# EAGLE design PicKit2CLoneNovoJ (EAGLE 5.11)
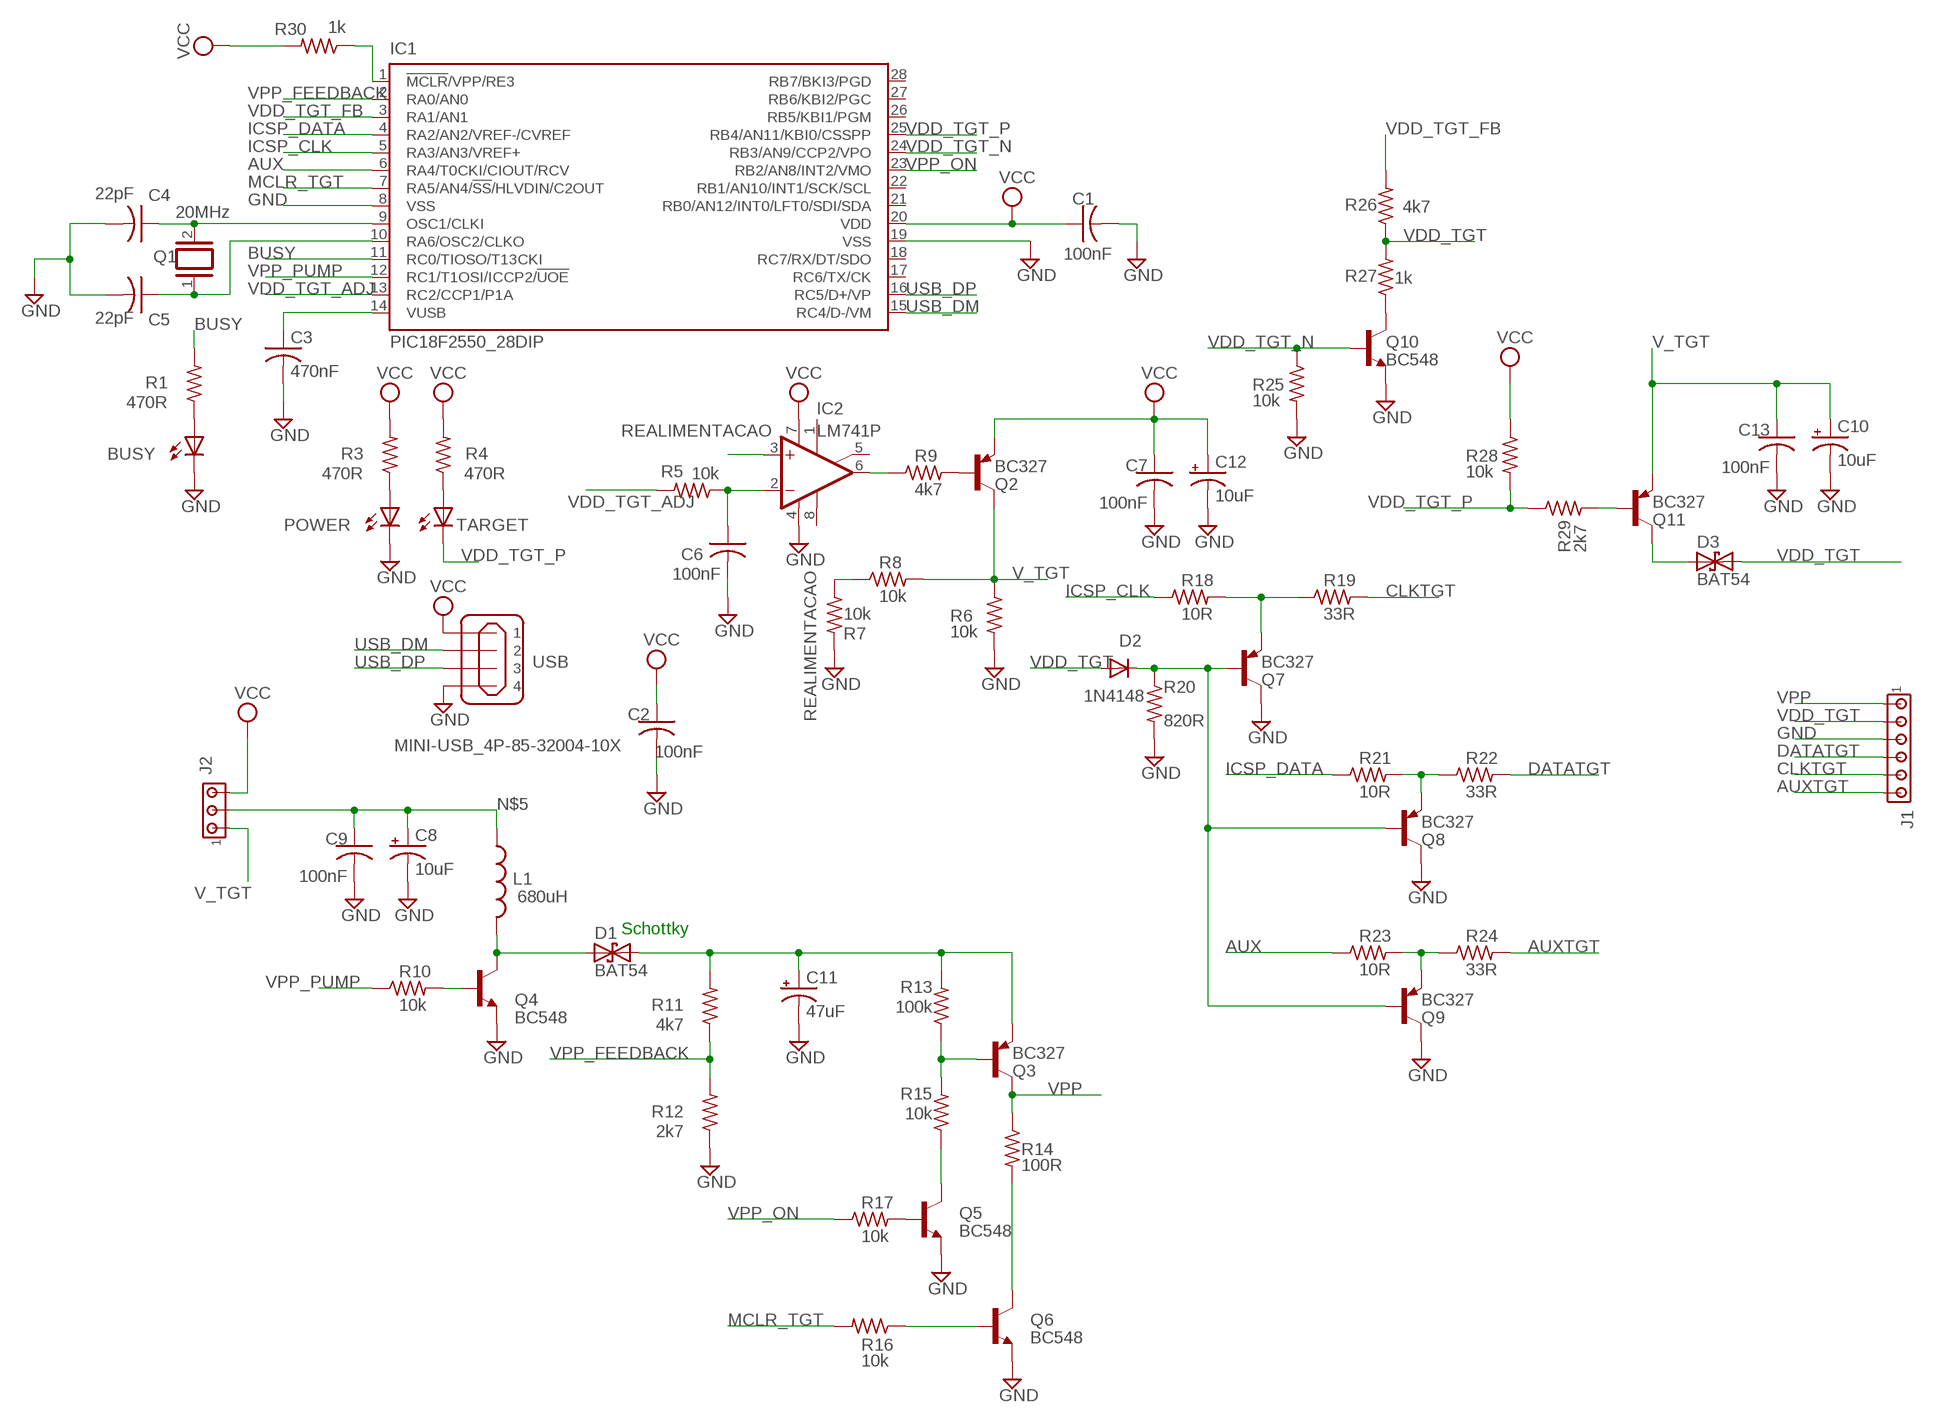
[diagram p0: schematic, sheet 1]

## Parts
BUSY  LED5MM  [LED5MM]
C1  100nF  C-US025-030X050  [C025-030X050]
C2  100nF  C-US025-030X050  [C025-030X050]
C3  470nF  C-US025-030X050  [C025-030X050]
C4  22pF  C-US025-025X050  [C025-025X050]
C5  22pF  C-US025-025X050  [C025-025X050]
C6  100nF  C-US025-030X050  [C025-030X050]
C7  100nF  C-US025-030X050  [C025-030X050]
C8  10uF  CPOL-USE1.8-4  [E1,8-4]
C9  100nF  C-US025-030X050  [C025-030X050]
C10  10uF  CPOL-USE1.8-4  [E1,8-4]
C11  47uF  CPOL-USE2.5-7  [E2,5-7]
C12  10uF  CPOL-USE1.8-4  [E1,8-4]
C13  100nF  C-US025-030X050  [C025-030X050]
D1  BAT54  DIODE_SCHOTTKY2-F126-12  [F126Z12]
D2  1N4148  1N4148DO35-10  [DO35-10]
D3  BAT54  DIODE_SCHOTTKY2-F126-12  [F126Z12]
IC1  PIC18F2550_28DIP  [DIL28-3]
IC2  LM741P  [DIL08]
J1  MTA06-100  [10X06MTA]
J2  MTA03-100  [10X03MTA]
L1  680uH  L-US0207/10  [0207/10]
POWER  LED5MM  [LED5MM]
Q1  20MHz  XTAL/S  [QS]
Q2  BC327  [TO92]
Q3  BC327  [TO92]
Q4  BC548  [TO92-EBC]
Q5  BC548  [TO92-EBC]
Q6  BC548  [TO92-EBC]
Q7  BC327  [TO92]
Q8  BC327  [TO92]
Q9  BC327  [TO92]
Q10  BC548  [TO92-EBC]
Q11  BC327  [TO92]
R1  470R  R-US_0207/10  [0207/10]
R3  470R  R-US_0207/10  [0207/10]
R4  470R  R-US_0207/10  [0207/10]
R5  10k  R-US_0207/10  [0207/10]
R6  10k  R-US_0207/10  [0207/10]
R7  10k  R-US_0207/10  [0207/10]
R8  10k  R-US_0207/10  [0207/10]
R9  4k7  R-US_0207/10  [0207/10]
R10  10k  R-US_0207/10  [0207/10]
R11  4k7  R-US_0207/10  [0207/10]
R12  2k7  R-US_0207/10  [0207/10]
R13  100k  R-US_0207/10  [0207/10]
R14  100R  R-US_0207/10  [0207/10]
R15  10k  R-US_0207/10  [0207/10]
R16  10k  R-US_0207/10  [0207/10]
R17  10k  R-US_0207/10  [0207/10]
R18  10R  R-US_0207/10  [0207/10]
R19  33R  R-US_0207/10  [0207/10]
R20  820R  R-US_0207/10  [0207/10]
R21  10R  R-US_0207/10  [0207/10]
R22  33R  R-US_0207/10  [0207/10]
R23  10R  R-US_0207/10  [0207/10]
R24  33R  R-US_0207/10  [0207/10]
R25  10k  R-US_0207/10  [0207/10]
R26  4k7  R-US_0207/10  [0207/10]
R27  1k  R-US_0207/10  [0207/10]
R28  10k  R-US_0207/10  [0207/10]
R29  2k7  R-US_0207/10  [0207/10]
R30  1k  R-US_0207/10  [0207/10]
TARGET  LED5MM  [LED5MM]
USB  MINI-USB_4P-85-32004-10X  [85-32004-10X]

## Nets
AUX: IC1.6(RA4/T0CKI/CIOUT/RCV) R23.1
AUXTGT: J1.1 R24.2
BUSY: IC1.11(RC0/TIOSO/T13CKI) R1.2
CLKTGT: J1.2 R19.2
DATATGT: J1.3 R22.2
GND: BUSY.K(C) C1.2 C2.2 C3.2 C4.2 C5.2 C6.2 C7.2 C8.- C9.2 C10.- C11.- C12.- C13.2 IC1.8(VSS) IC1.19(VSS) IC2.4(V-) J1.4 POWER.K(C) Q4.E Q5.E Q6.E Q7.3(C) Q8.3(C) Q9.3(C) Q10.E R6.2 R7.2 R12.1 R20.2 R25.2 USB.4
ICSP_CLK: IC1.5(RA3/AN3/VREF+) R18.1
ICSP_DATA: IC1.4(RA2/AN2/VREF-/CVREF) R21.1
MCLR_TGT: IC1.7(RA5/AN4/!SS!/HLVDIN/C2OUT) R16.2
N$1: C4.1 IC1.9(OSC1/CLKI) Q1.2
N$2: C5.1 IC1.10(RA6/OSC2/CLKO) Q1.1
N$3: BUSY.A R1.1
N$4: C3.1 IC1.14(VUSB)
N$5: C8.+ C9.1 J2.2 L1.1
N$7: POWER.A R3.1
N$8: R4.1 TARGET.A
N$9: C6.1 IC2.2(-IN) R5.1
N$10: Q2.2(B) R9.2
N$11: IC2.6(OUT) R9.1
N$12: D1.A L1.2 Q4.C
N$14: IC1.1(!MCLR!/VPP/RE3) R30.1
N$15: Q4.B R10.2
N$16: Q5.C R15.1
N$17: C11.+ D1.C Q3.1(E) R11.2 R13.2
N$18: Q5.B R17.2
N$19: Q3.2(B) R13.1 R15.2
N$20: D2.C Q7.2(B) Q8.2(B) Q9.2(B) R20.1
N$21: Q6.B R16.1
N$22: Q7.1(E) R18.2 R19.1
N$23: Q6.C R14.2
N$24: Q8.1(E) R21.2 R22.1
N$25: Q9.1(E) R23.2 R24.1
N$26: Q10.C R27.1
N$27: Q11.2(B) R29.2
N$30: D3.A Q11.3(C)
REALIMENTACAO: IC2.3(+IN) R7.1 R8.1
USB_DM: IC1.15(RC4/D-/VM) USB.2
USB_DP: IC1.16(RC5/D+/VP) USB.3
V_TGT: C10.+ C13.1 J2.1 Q2.3(C) Q11.1(E) R6.1 R8.2
VCC: C1.1 C2.1 C7.1 C12.+ IC1.20(VDD) IC2.7(V+) J2.3 Q2.1(E) R3.2 R4.2 R28.1 R30.2 USB.1
VDD_TGT: D2.A D3.C J1.5 R26.1 R27.2
VDD_TGT_ADJ: IC1.13(RC2/CCP1/P1A) R5.2
VDD_TGT_FB: IC1.3(RA1/AN1) R26.2
VDD_TGT_N: IC1.24(RB3/AN9/CCP2/VPO) Q10.B R25.1
VDD_TGT_P: IC1.25(RB4/AN11/KBI0/CSSPP) R28.2 R29.1 TARGET.K(C)
VPP: J1.6 Q3.3(C) R14.1
VPP_FEEDBACK: IC1.2(RA0/AN0) R11.1 R12.2
VPP_ON: IC1.23(RB2/AN8/INT2/VMO) R17.1
VPP_PUMP: IC1.12(RC1/T1OSI/ICCP2/!UOE) R10.1
Unconnected: IC1.17(RC6/TX/CK) IC1.18(RC7/RX/DT/SDO) IC1.21(RB0/AN12/INT0/LFT0/SDI/SDA) IC1.22(RB1/AN10/INT1/SCK/SCL) IC1.26(RB5/KBI1/PGM) IC1.27(RB6/KBI2/PGC) IC1.28(RB7/BKI3/PGD) IC2.1(ON1) IC2.5(ON2) IC2.8(OPT)

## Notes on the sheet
- Schottky

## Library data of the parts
BUSY POWER TARGET = led:LED: LED
C1-C7 C9 C13 = rcl:C-US: CAPACITOR, American symbol
C8 C10-C12 = resistor:CPOL-US: POLARIZED CAPACITOR, American symbol
D1 D3 = diode:DIODE_SCHOTTKY2-: Schottky Bidirectional Diode
D2 = diode:1N4148: DIODE
IC1 = microchip:PIC18F2*_28: USB Microcontrollers with nanoWatt Technology High-Performance, Enhanced Flash, 28/40/44-Pin, Source: http://ww1.microchip.com/downloads/en/devicedoc/39632c.pdf; MF: MICROCHIP; MPN: PIC18F2550-I/SP; OC_FARNELL: 1523822; OC_NEWARK: 80K6054
IC2 = linear:*741: OP AMP
J1 = con-amp:MTA06-100: AMP connector; OC_FARNELL: unknown; OC_NEWARK: unknown
J2 = con-amp:MTA03-100: AMP connector; OC_FARNELL: unknown; OC_NEWARK: unknown
L1 = rcl:L-US: INDUCTOR, American symbol
Q1 = special:XTAL/S: CRYSTAL
Q2 Q3 Q7-Q9 Q11 = transistor-pnp:BC327: PNP Transistor
Q4-Q6 Q10 = transistor-npn:BC548*: NPN Transistor
R1 R3-R30 = rcl:R-US_: RESISTOR, American symbol
USB = con-cypressindustries:MINI-USB_4P-: MINI USB 4 Pol. Source: www.cypressindustries.com; OC_FARNELL: unknown; OC_NEWARK: unknown

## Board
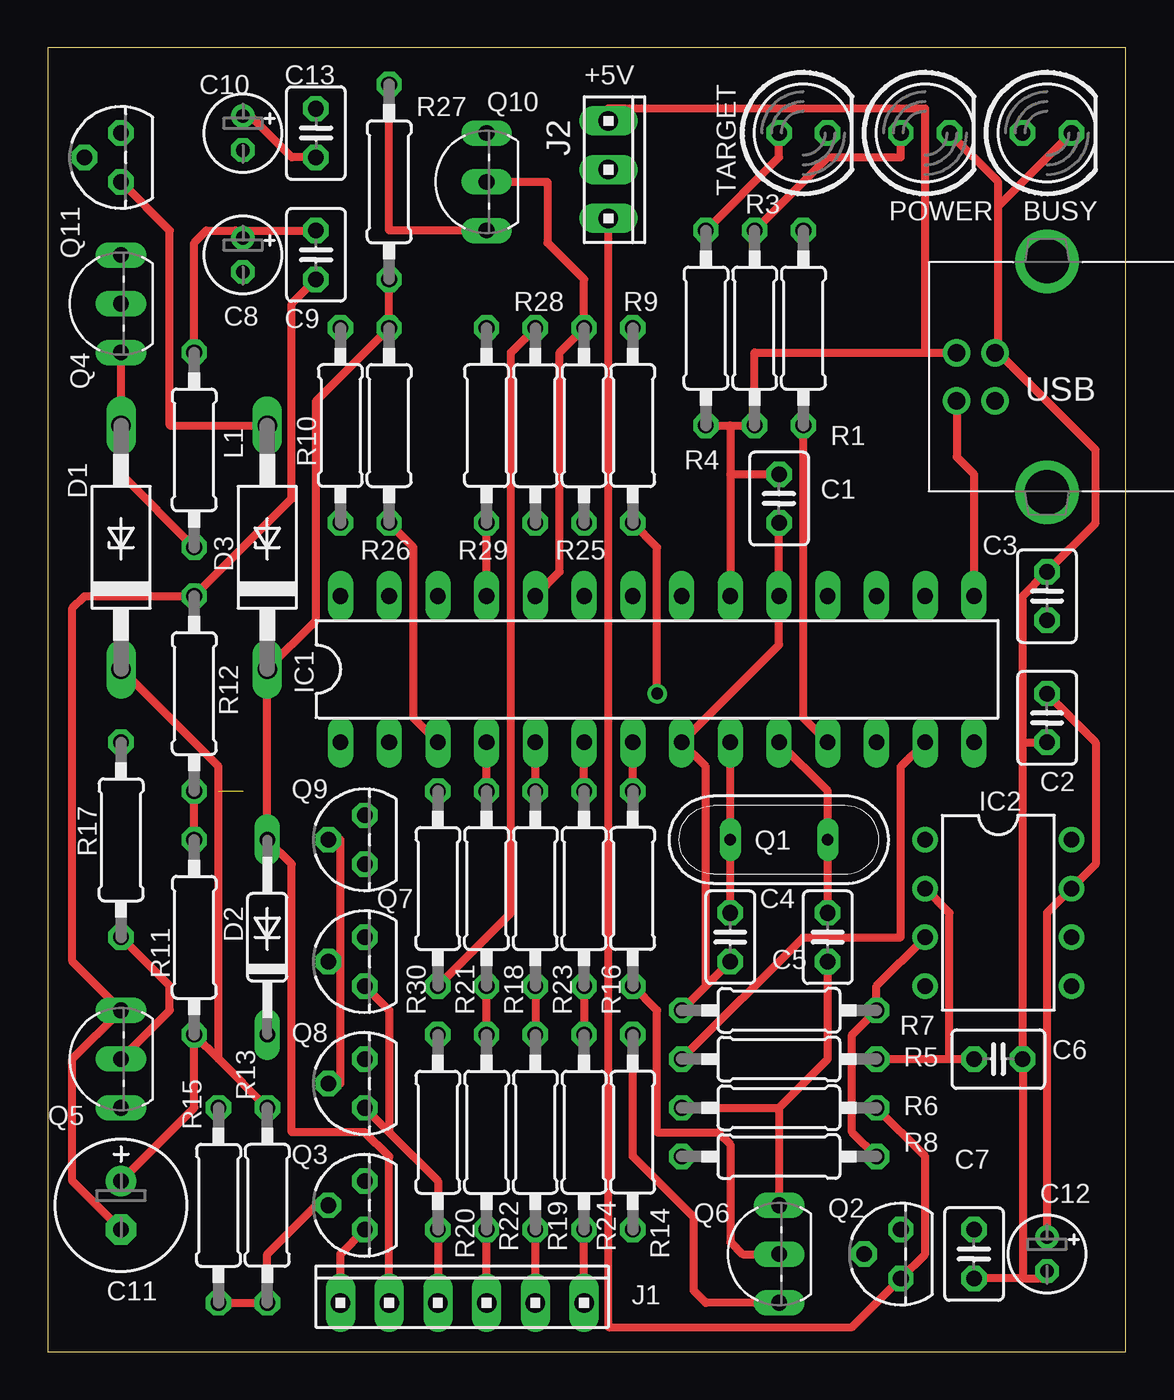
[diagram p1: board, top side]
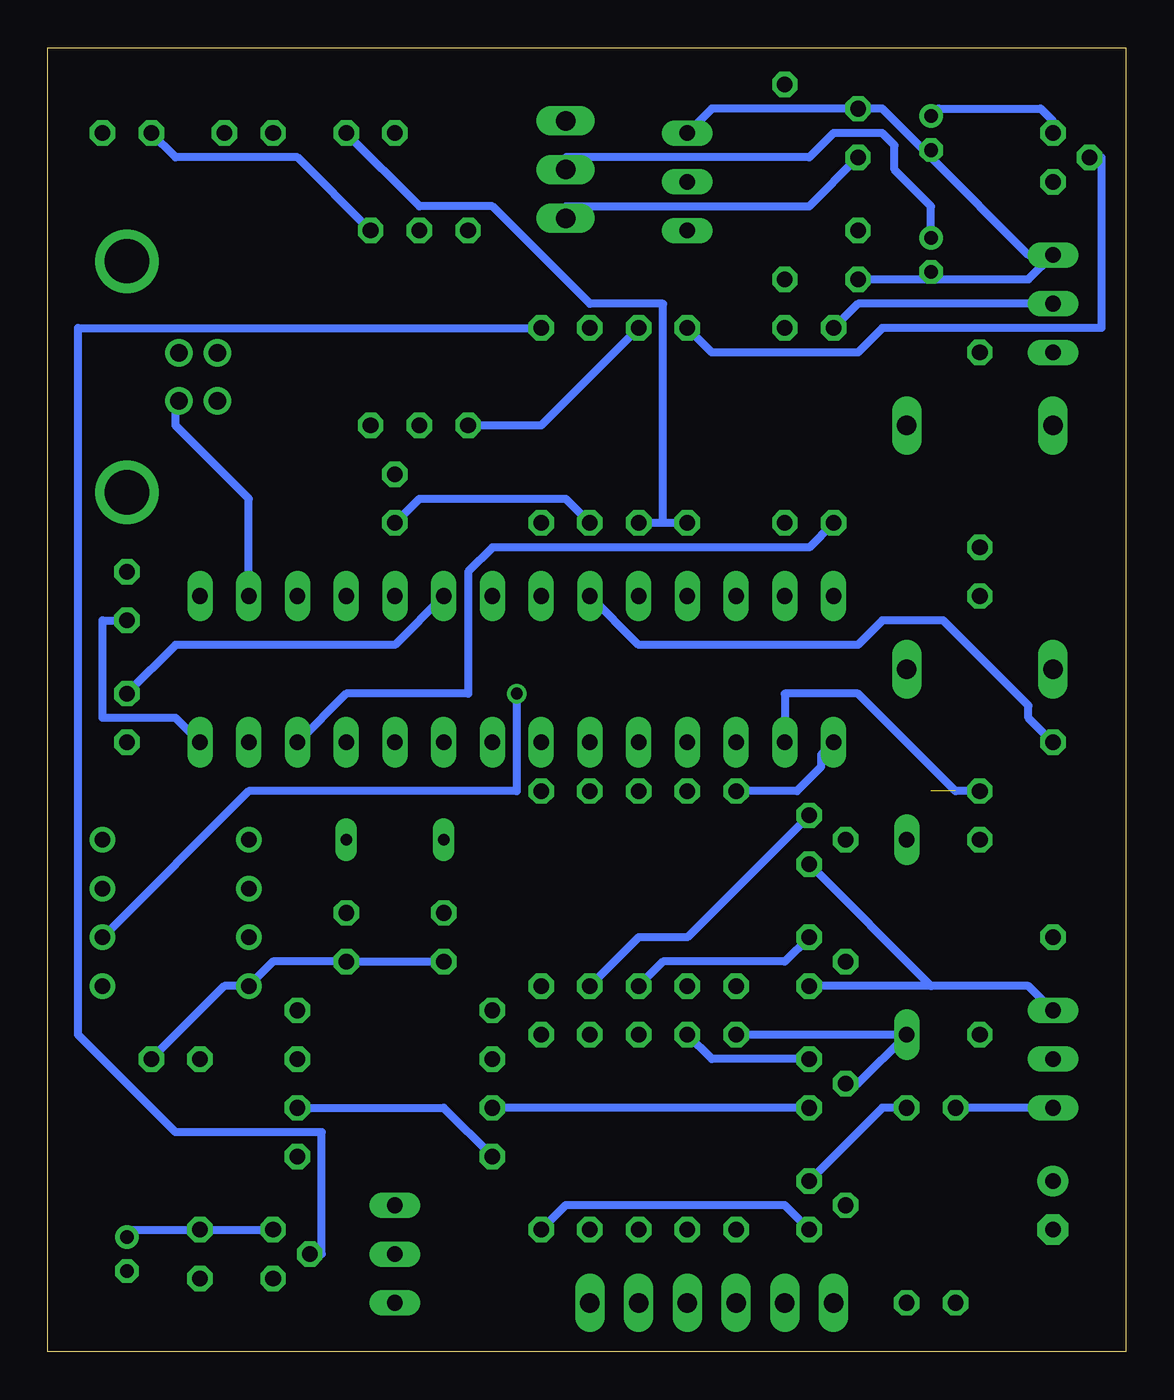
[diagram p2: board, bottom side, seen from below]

Size 56.19 x 67.94 mm. Coordinates in mm from the lower left corner, seen from the top.
Outline: 0,0 56.19,0 56.19,67.94 0,67.94 0,0
Copper layers (1*16): Top 0.035mm / dielectric 1.5mm / Bottom 0.035mm
Design rules "default *": minimum track width 16mil, minimum drill 24mil, track to track 12mil, track to pad 12mil, pad to pad 12mil, via to via 12mil, smd to smd 8mil, copper to edge 40mil, drill to drill 12mil, minimum pad ring 10mil, minimum via ring 8mil, stop-mask expansion 4mil, vias tented up to drill 0mil, thermal gap 10mil

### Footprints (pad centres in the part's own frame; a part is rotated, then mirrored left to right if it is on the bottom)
LED5MM = drill 0.813 octagon: A -1.27,0; K 1.27,0
C025-030X050 = drill 0.813 octagon: 1 -1.27,0; 2 1.27,0
C025-025X050 = drill 0.813 octagon: 1 -1.27,0; 2 1.27,0
E1,8-4 = drill 0.711 pad 1.168 round: + -0.889,0 | drill 0.711 pad 1.168 octagon: - 0.889,0
E2,5-7 = drill 0.813 pad 1.6 round: + -1.27,0 | drill 0.813 pad 1.6 octagon: - 1.27,0
F126Z12 = drill 1.016 long: A 6.35,0; C -6.35,0
DO35-10 = drill 0.813 long: A 5.08,0; C -5.08,0
DIL28-3 = drill 0.813 long: 1 -16.51,-3.81; 2 -13.97,-3.81; 3 -11.43,-3.81; 4 -8.89,-3.81; 5 -6.35,-3.81; 6 -3.81,-3.81; 7 -1.27,-3.81; 8 1.27,-3.81; 9 3.81,-3.81; 10 6.35,-3.81; 11 8.89,-3.81; 12 11.43,-3.81; 13 13.97,-3.81; 14 16.51,-3.81; 15 16.51,3.81; 16 13.97,3.81; 17 11.43,3.81; 18 8.89,3.81; 19 6.35,3.81; 20 3.81,3.81; 21 1.27,3.81; 22 -1.27,3.81; 23 -3.81,3.81; 24 -6.35,3.81; 25 -8.89,3.81; 26 -11.43,3.81; 27 -13.97,3.81; 28 -16.51,3.81
DIL08 = drill 0.813 pad 1.27 round: 1 -3.81,-3.81; 2 -1.27,-3.81; 3 1.27,-3.81; 4 3.81,-3.81; 5 3.81,3.81; 6 1.27,3.81; 7 -1.27,3.81; 8 -3.81,3.81
10X06MTA = drill 1.016 long: 1 6.35,0; 2 3.81,0; 3 1.27,0; 4 -1.27,0; 5 -3.81,0; 6 -6.35,0
10X03MTA = drill 1.016 long: 1 2.54,0; 2 0,0; 3 -2.54,0
0207/10 = drill 0.813 octagon: 1 -5.08,0; 2 5.08,0
QS = drill 0.61 long: 1 -2.54,0; 2 2.54,0
TO92 = drill 0.813 octagon: 1 1.27,0; 2 0,1.905; 3 -1.27,0
TO92-EBC = drill 0.813 long: B 0,-1.27; C -2.54,-1.27; E 2.54,-1.27
85-32004-10X = drill 0.92 pad 1.27 round: 1 4.71,-1.25; 2 4.71,1.25; 3 2.71,1.25; 4 2.71,-1.25 | drill 2.3 pad 3 round: M1 0,6.02; M2 0,-6.02

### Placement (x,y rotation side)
BUSY  52.07,63.5 0 top
C1  38.1,44.45 270 top
C2  52.07,33.02 270 top
C3  52.07,39.37 90 top
C4  35.56,21.59 270 top
C5  40.64,21.59 270 top
C6  49.53,15.24 0 top
C7  48.26,5.08 270 top
C8  10.16,57.15 270 top
C9  13.97,57.15 270 top
C10  10.16,63.5 270 top
C11  3.81,7.62 270 top
C12  52.07,5.08 270 top
C13  13.97,63.5 90 top
D1  3.81,41.91 90 top
D2  11.43,21.59 90 top
D3  11.43,41.91 90 top
IC1  31.75,35.56 0 top
IC2  49.53,22.86 270 top
J1  21.59,2.54 0 top
J2  29.21,61.6 270 top
L1  7.62,46.99 270 top
POWER  45.72,63.5 0 top
Q1  38.1,26.67 180 top
Q2  44.45,5.08 90 top
Q3  16.51,7.62 90 top
Q4  2.54,54.61 90 top
Q5  2.54,15.24 90 top
Q6  36.83,5.08 90 top
Q7  16.51,20.32 90 top
Q8  16.51,13.97 90 top
Q9  16.51,26.67 90 top
Q10  21.59,60.96 90 top
Q11  3.81,62.23 90 top
R1  39.37,53.34 270 top
R3  36.83,53.34 270 top
R4  34.29,53.34 270 top
R5  38.1,15.24 180 top
R6  38.1,12.7 180 top
R7  38.1,17.78 180 top
R8  38.1,10.16 180 top
R9  30.48,48.26 90 top
R10  15.24,48.26 90 top
R11  7.62,21.59 270 top
R12  7.62,34.29 270 top
R13  11.43,7.62 90 top
R14  30.48,11.43 90 top
R15  8.89,7.62 270 top
R16  30.48,24.13 90 top
R17  3.81,26.67 270 top
R18  25.4,24.13 270 top
R19  25.4,11.43 270 top
R20  20.32,11.43 270 top
R21  22.86,24.13 270 top
R22  22.86,11.43 270 top
R23  27.94,24.13 270 top
R24  27.94,11.43 270 top
R25  27.94,48.26 270 top
R26  17.78,48.26 270 top
R27  17.78,60.96 270 top
R28  25.4,48.26 270 top
R29  22.86,48.26 90 top
R30  20.32,24.13 270 top
TARGET  39.37,63.5 0 top
USB  52.07,50.8 180 top

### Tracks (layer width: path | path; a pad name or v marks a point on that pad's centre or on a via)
AUX
  Top 0.406: R23.1 IC1.6
AUXTGT
  Top 0.406: J1.1 R24.2
BUSY
  Top 0.406: IC1.11 39.37,33.02 R1.2
CLKTGT
  Top 0.406: J1.2 R19.2
DATATGT
  Top 0.406: J1.3 R22.2
GND
  Top 0.406: C9.2 12.7,54.61 12.7,44.45 R12.1 1.91,39.37 1.27,38.73 1.27,20.32 Q5.E 1.27,15.24 1.27,8.89 C11.- | C1.2 IC1.19 38.1,36.83 IC1.8 34.29,30.48 34.29,19.05 | POWER.K 49.53,60.96 49.53,59.69 | 49.53,52.07 49.53,59.69 | 49.53,59.69 BUSY.K | J1.4 R20.2 20.32,8.89 17.78,11.43 | 17.78,11.43 Q8.3 | R6.2 38.1,12.7 | 38.1,12.7 Q6.E | C4.2 34.29,19.05 | 34.29,19.05 R7.2 | 50.8,3.81 C7.2 | 50.8,3.81 52.07,3.81 C12.- | 50.8,31.75 C6.2 50.8,3.81 | 50.8,31.75 50.8,39.37 C3.2 54.61,43.18 54.61,46.99 49.53,52.07 | 38.1,12.7 40.64,15.24 C5.2 | 49.53,52.07 USB.4 | Q7.3 17.78,17.78 17.78,11.43 | 50.8,31.75 C2.2
  Bottom 0.406: 10.16,62.23 12.7,64.77 C13.2 21.59,64.77 Q10.E | C9.2 10.16,55.88 | 10.16,55.88 5.08,55.88 Q4.E 5.08,57.15 10.16,62.23 | 10.16,55.88 C8.- | 10.16,62.23 C10.- | Q5.E 5.08,19.05 10.16,19.05 | 10.16,19.05 Q7.3 | 10.16,19.05 Q9.3 | R25.2 29.21,44.45 36.83,44.45 C1.2 | C6.2 46.99,19.05 IC2.4 44.45,20.32 C5.2 C4.2 | Q8.3 R6.2
ICSP_CLK
  Top 0.406: R18.1 IC1.5
ICSP_DATA
  Top 0.406: R21.1 IC1.4
MCLR_TGT
  Top 0.406: R16.2 IC1.7
N$1
  Top 0.406: C4.1 Q1.2 IC1.9
N$2
  Top 0.406: C5.1 Q1.1 40.64,29.21 IC1.10
N$3
  Bottom 0.406: R1.1 43.18,62.23 49.53,62.23 BUSY.A
N$4
  Bottom 0.406: IC1.14 49.53,33.02 53.34,33.02 53.34,38.1 C3.1
N$5
  Top 0.406: C9.1 10.16,58.42 C8.+ 9.78,58.42 8.25,58.42 7.62,57.79 L1.1
  Bottom 0.406: J2.2 29.21,62.23 16.51,62.23 15.24,63.5 12.7,63.5 12.06,62.87 12.06,61.6 10.16,59.69 C8.+
N$7
  Top 0.406: R3.1 40.64,62.23 44.45,62.23 POWER.A
N$8
  Top 0.406: R4.1 38.1,62.23 TARGET.A
N$9
  Top 0.406: 46.99,15.24 C6.1 | R5.1 46.99,15.24 | IC2.2 46.99,22.86 46.99,15.24
N$10
  Bottom 0.406: R9.2 54.61,53.34 54.61,16.51 49.53,11.43 41.91,11.43 41.91,5.08 Q2.2
N$11  (via drill 0.61)
  Top 0.406: R9.1 31.75,41.91 v31.75,34.29
  Bottom 0.406: v31.75,34.29 31.75,29.21 45.72,29.21 IC2.6
N$12
  Top 0.406: Q4.C D1.A 3.81,45.72 L1.2
N$14
  Bottom 0.406: R30.1 17.15,29.21 15.88,30.48 15.88,31.11 IC1.1
N$15
  Bottom 0.406: Q4.B 13.97,54.61 R10.2
N$16
  Bottom 0.406: Q5.C R15.1
N$17
  Top 0.406: 8.89,15.24 R13.2 | 8.89,15.24 R11.2 7.62,12.7 C11.+ | D1.C 8.89,30.48 8.89,15.24
  Bottom 0.406: Q3.1 12.7,12.7 R13.2
N$18
  Top 0.406: Q5.B 6.35,17.78 6.35,19.05 R17.2
N$19
  Top 0.406: R15.2 R13.1 11.43,5.08 13.97,7.62 Q3.2
N$20
  Top 0.406: 15.24,20.32 15.24,26.67 Q9.2 | 15.24,20.32 15.24,13.97 Q8.2 | 15.24,20.32 Q7.2
  Bottom 0.406: Q8.2 13.97,13.97 D2.C R20.1
N$21
  Top 0.406: R16.1 31.75,17.78 31.75,11.43 34.92,11.43 35.56,10.79 35.56,5.72 36.2,5.08 Q6.B
N$22
  Top 0.406: R18.2 R19.1
  Bottom 0.406: Q7.1 17.78,20.32 24.13,20.32 R18.2
N$23
  Top 0.406: R14.2 30.48,10.16 33.66,6.99 33.66,3.17 34.29,2.54 Q6.C
N$24
  Top 0.406: R22.1 R21.2
  Bottom 0.406: Q8.1 21.59,15.24 R22.1
N$25
  Top 0.406: R23.2 R24.1
  Bottom 0.406: Q9.1 22.86,21.59 25.4,21.59 R23.2
N$26
  Top 0.406: Q10.C 17.78,58.42 R27.1
N$27
  Bottom 0.406: R29.2 21.59,52.07 13.97,52.07 12.7,53.34 1.27,53.34 1.27,62.23 Q11.2
N$30
  Top 0.406: Q11.3 6.35,58.42 6.35,48.26 D3.A
REALIMENTACAO
  Top 0.406: R8.1 41.91,11.43 41.91,16.51 R7.1 43.18,19.05 IC2.3
USB_DM
  Top 0.406: USB.2 47.36,46.62 48.26,45.72 IC1.15
USB_DP
  Bottom 0.406: IC1.16 45.72,44.45 49.53,48.26 49.53,49.38 USB.3
V_TGT
  Top 0.406: R6.1 45.72,10.16 45.72,5.08 Q2.3 41.91,1.27 29.21,1.27 J2.1 | C13.1 12.7,62.23 10.16,64.77 C10.+
  Bottom 0.406: R8.2 35.56,12.7 R6.1 | 10.16,64.77 C10.+ 9.78,64.77 4.45,64.77 3.81,64.13 Q11.1 | C13.1 16.51,59.69 29.21,59.69 J2.1
VCC
  Top 0.406: R30.2 24.13,22.86 24.13,52.07 R28.1 | C12.+ 52.07,22.86 IC2.7 54.61,25.4 54.61,31.75 C2.1 | 35.56,48.26 R3.2 36.83,52.07 45.72,52.07 | R4.2 35.56,48.26 | 35.56,48.26 35.56,45.72 | 35.56,45.72 IC1.20 | 35.56,45.72 C1.1 | 45.72,52.07 46.99,52.07 USB.1 | 45.72,52.07 45.72,64.77 29.21,64.77 J2.3
  Bottom 0.406: C12.+ 52.07,6.35 C7.1 Q2.1 | C2.1 49.53,36.83 38.1,36.83 IC1.20 | R28.1 30.48,48.26 R4.2
VDD_TGT
  Top 0.406: R27.2 R26.1 13.97,49.53 13.97,38.1 D3.C D2.A 12.7,25.4 12.7,11.43 16.51,11.43 17.78,10.16 J1.5
VDD_TGT_ADJ
  Top 0.406: R5.2 39.37,21.59 44.45,21.59 44.45,30.48 IC1.13
VDD_TGT_FB
  Top 0.406: IC1.3 19.05,33.02 19.05,41.91 R26.2
VDD_TGT_N
  Top 0.406: IC1.24 26.67,40.64 26.67,52.07 R25.1 27.94,55.88 26.04,57.79 26.04,60.96 Q10.B
VDD_TGT_P
  Top 0.406: IC1.25 R29.1
  Bottom 0.406: R29.1 24.13,43.18 | 24.13,43.18 R28.2 | TARGET.K 36.83,59.69 33.02,59.69 27.94,54.61 24.13,54.61 24.13,43.18
VPP
  Top 0.406: Q3.3 15.24,5.08 J1.6
  Bottom 0.406: R14.1 29.21,7.62 17.78,7.62 Q3.3
VPP_FEEDBACK  (1 unrouted)
  Top 0.406: R11.1 R12.2
  Bottom 0.406: R12.2 8.89,29.21 13.97,34.29 17.78,34.29 IC1.2
VPP_ON
  Bottom 0.406: R17.1 5.08,33.02 5.08,33.66 9.52,38.1 12.7,38.1 13.97,36.83 25.4,36.83 IC1.23
VPP_PUMP
  Bottom 0.406: R10.1 16.51,41.91 33.02,41.91 34.29,40.64 34.29,34.29 40.64,34.29 IC1.12

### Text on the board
tNames: +5V
tValues: 100nF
